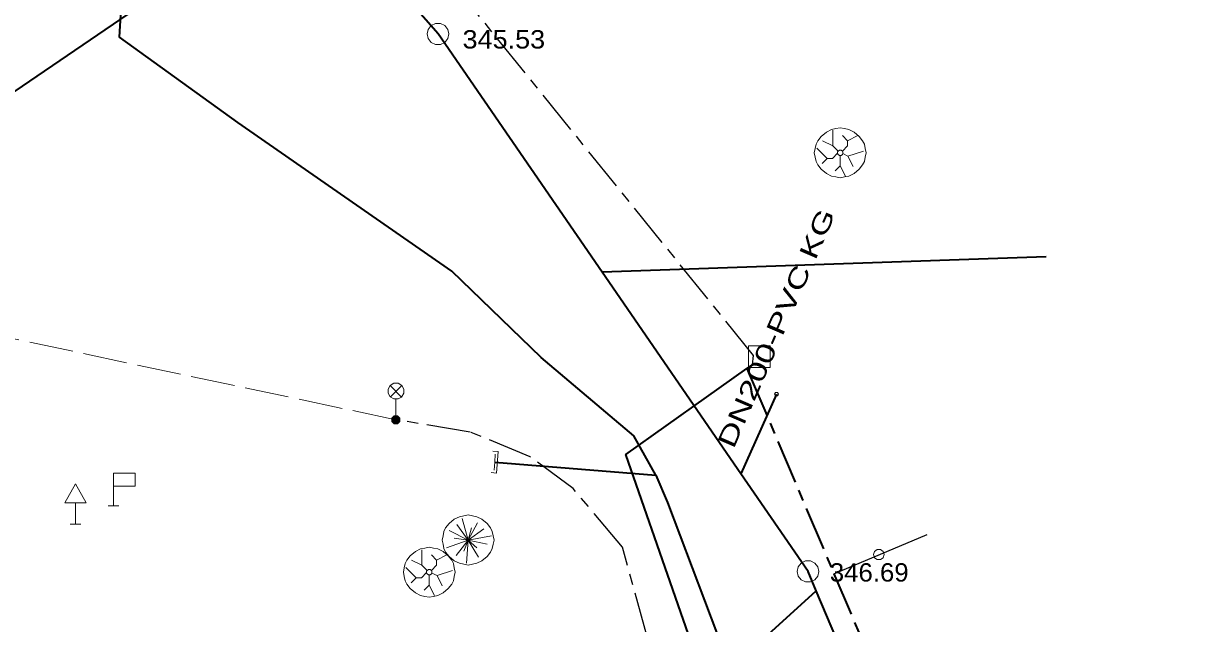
# Model space of a CAD drawing. Extents: x -763495 to -763378, y -1031793 to -1031652.
# Drawn here: x -763444.2 to -763390, y -1031751.8 to -1031723.9 of the extents above; entities that cross this region are included whole.
import ezdxf
from ezdxf.enums import TextEntityAlignment as Align

# ---------------------------------------------------------------- set-up
doc = ezdxf.new("R2010")
doc.units = 0
doc.header["$LTSCALE"] = 0.34
doc.linetypes.add('LONG_DASH_SHORT_DASH', pattern=[9.9, 6, -1.2, 1.5, -1.2])
doc.linetypes.add('LONG_DASHED', pattern=[7.5, 6, -1.5])
for name, color, linetype, lineweight in [('23', 7, 'Continuous', 13), ('27', 7, 'Continuous', 13), ('33', 7, 'Continuous', 13), ('34', 7, 'Continuous', 13), ('40', 7, 'Continuous', 13), ('43', 7, 'Continuous', 25), ('44', 7, 'Continuous', 35), ('45', 7, 'Continuous', 13), ('51', 7, 'LONG_DASH_SHORT_DASH', 25), ('59', 7, 'LONG_DASHED', 13)]:
    doc.layers.add(name, color=color, linetype=linetype, lineweight=lineweight)

msp = doc.modelspace()

# ---------------------------------------------------------------- linework, layer by layer
at = {"layer": '23'}
for p, q in [((-763440.31, -1031746.29), (-763439.81, -1031746.29)), ((-763442.07, -1031747.15), (-763441.57, -1031747.15))]:
    msp.add_line(p, q, dxfattribs=at)
for points in [[(-763440.06, -1031746.29), (-763440.06, -1031744.79), (-763439.06, -1031744.79), (-763439.06, -1031745.39), (-763440.06, -1031745.39)], [(-763441.82, -1031747.15), (-763441.82, -1031746.15), (-763441.32, -1031746.15), (-763441.82, -1031745.275), (-763442.32, -1031746.15), (-763441.82, -1031746.15)]]:
    msp.add_lwpolyline(points, dxfattribs=at)
at = {"layer": '27'}
for p, q in [((-763406.07, -1031729.38), (-763406.31, -1031729.14)), ((-763406.05, -1031730.1), (-763405.33, -1031729.86)), ((-763407.01, -1031730.2), (-763407.25, -1031730.44)), ((-763406.41, -1031730.54), (-763406.17, -1031731.02)), ((-763425.1, -1031748.81), (-763425.34, -1031748.57)), ((-763426.04, -1031749.63), (-763426.28, -1031749.87)), ((-763425.08, -1031749.53), (-763424.36, -1031749.29)), ((-763425.44, -1031749.97), (-763425.2, -1031750.45))]:
    msp.add_line(p, q, dxfattribs=at)
for points in [[(-763407.61, -1031729.94), (-763407.57, -1031729.74), (-763407.53, -1031729.54), (-763407.45, -1031729.38), (-763407.29, -1031729.18), (-763407.05, -1031728.98), (-763406.81, -1031728.86), (-763406.61, -1031728.82), (-763406.41, -1031728.78), (-763406.21, -1031728.82), (-763406.01, -1031728.86), (-763405.77, -1031728.98), (-763405.53, -1031729.18), (-763405.37, -1031729.38), (-763405.29, -1031729.54), (-763405.25, -1031729.74), (-763405.21, -1031729.94), (-763405.25, -1031730.14), (-763405.29, -1031730.34), (-763405.37, -1031730.5), (-763405.53, -1031730.7), (-763405.77, -1031730.9), (-763406.01, -1031731.02), (-763406.21, -1031731.06), (-763406.41, -1031731.1), (-763406.61, -1031731.06), (-763406.81, -1031731.02), (-763407.05, -1031730.9), (-763407.29, -1031730.7), (-763407.45, -1031730.5), (-763407.53, -1031730.34), (-763407.57, -1031730.14)], [(-763406.53, -1031729.94), (-763406.53, -1031729.9), (-763406.51, -1031729.86), (-763406.45, -1031729.82), (-763406.37, -1031729.82), (-763406.31, -1031729.86), (-763406.29, -1031729.9), (-763406.29, -1031729.98), (-763406.31, -1031730.02), (-763406.37, -1031730.06), (-763406.45, -1031730.06), (-763406.51, -1031730.02), (-763406.53, -1031729.98)], [(-763424.84, -1031747.88), (-763424.8, -1031747.68), (-763424.76, -1031747.48), (-763424.68, -1031747.32), (-763424.52, -1031747.12), (-763424.28, -1031746.92), (-763424.04, -1031746.8), (-763423.84, -1031746.76), (-763423.64, -1031746.72), (-763423.44, -1031746.76), (-763423.24, -1031746.8), (-763423, -1031746.92), (-763422.76, -1031747.12), (-763422.6, -1031747.32), (-763422.52, -1031747.48), (-763422.48, -1031747.68), (-763422.44, -1031747.88), (-763422.48, -1031748.08), (-763422.52, -1031748.28), (-763422.6, -1031748.44), (-763422.76, -1031748.64), (-763423, -1031748.84), (-763423.24, -1031748.96), (-763423.44, -1031749), (-763423.64, -1031749.04), (-763423.84, -1031749), (-763424.04, -1031748.96), (-763424.28, -1031748.84), (-763424.52, -1031748.64), (-763424.68, -1031748.44), (-763424.76, -1031748.28), (-763424.8, -1031748.08)], [(-763426.64, -1031749.37), (-763426.6, -1031749.17), (-763426.56, -1031748.97), (-763426.48, -1031748.81), (-763426.32, -1031748.61), (-763426.08, -1031748.41), (-763425.84, -1031748.29), (-763425.64, -1031748.25), (-763425.44, -1031748.21), (-763425.24, -1031748.25), (-763425.04, -1031748.29), (-763424.8, -1031748.41), (-763424.56, -1031748.61), (-763424.4, -1031748.81), (-763424.32, -1031748.97), (-763424.28, -1031749.17), (-763424.24, -1031749.37), (-763424.28, -1031749.57), (-763424.32, -1031749.77), (-763424.4, -1031749.93), (-763424.56, -1031750.13), (-763424.8, -1031750.33), (-763425.04, -1031750.45), (-763425.24, -1031750.49), (-763425.44, -1031750.53), (-763425.64, -1031750.49), (-763425.84, -1031750.45), (-763426.08, -1031750.33), (-763426.32, -1031750.13), (-763426.48, -1031749.93), (-763426.56, -1031749.77), (-763426.6, -1031749.57)], [(-763425.56, -1031749.37), (-763425.56, -1031749.33), (-763425.54, -1031749.29), (-763425.48, -1031749.25), (-763425.4, -1031749.25), (-763425.34, -1031749.29), (-763425.32, -1031749.33), (-763425.32, -1031749.41), (-763425.34, -1031749.45), (-763425.4, -1031749.49), (-763425.48, -1031749.49), (-763425.54, -1031749.45), (-763425.56, -1031749.41)]]:
    msp.add_lwpolyline(points, close=True, dxfattribs=at)
for points in [[(-763406.51, -1031729.86), (-763406.75, -1031729.62), (-763406.75, -1031728.9), (-763406.75, -1031729.62), (-763407.23, -1031729.38)], [(-763406.31, -1031729.86), (-763406.07, -1031729.62), (-763406.07, -1031729.38), (-763405.59, -1031729.14)], [(-763406.53, -1031729.96), (-763406.77, -1031730.2), (-763407.01, -1031730.2), (-763407.49, -1031729.72)], [(-763406.41, -1031730.06), (-763406.41, -1031730.54), (-763406.65, -1031730.78)], [(-763406.29, -1031729.98), (-763406.05, -1031730.1), (-763405.81, -1031730.58)], [(-763423.48, -1031747.32), (-763423.64, -1031747.88), (-763423.92, -1031746.88), (-763423.64, -1031747.88), (-763424.16, -1031747.16), (-763423.64, -1031747.88), (-763424.52, -1031747.44), (-763423.64, -1031747.88), (-763424.28, -1031747.8), (-763423.64, -1031747.88), (-763424.64, -1031748.24), (-763423.64, -1031747.88), (-763424.2, -1031748.6), (-763423.64, -1031747.88), (-763423.84, -1031748.4), (-763423.64, -1031747.88), (-763423.72, -1031748.96), (-763423.64, -1031747.88), (-763423.16, -1031748.68), (-763423.64, -1031747.88), (-763423.24, -1031748.24), (-763423.64, -1031747.88), (-763422.76, -1031748.08), (-763423.64, -1031747.88), (-763422.56, -1031747.68), (-763423.64, -1031747.88), (-763422.92, -1031747.36), (-763423.64, -1031747.88), (-763423.2, -1031747.08), (-763423.64, -1031747.88)], [(-763425.54, -1031749.29), (-763425.78, -1031749.05), (-763425.78, -1031748.33), (-763425.78, -1031749.05), (-763426.26, -1031748.81)], [(-763425.34, -1031749.29), (-763425.1, -1031749.05), (-763425.1, -1031748.81), (-763424.62, -1031748.57)], [(-763425.56, -1031749.39), (-763425.8, -1031749.63), (-763426.04, -1031749.63), (-763426.52, -1031749.15)], [(-763425.44, -1031749.49), (-763425.44, -1031749.97), (-763425.68, -1031750.21)], [(-763425.32, -1031749.41), (-763425.08, -1031749.53), (-763424.84, -1031750.01)]]:
    msp.add_lwpolyline(points, dxfattribs=at)
at = {"layer": '33'}
for points in [[(-763410.66, -1031738.88), (-763409.66, -1031738.88), (-763409.66, -1031739.88), (-763410.66, -1031739.88)], [(-763404.545, -1031748.32), (-763404.42, -1031748.41), (-763404.37, -1031748.555), (-763404.42, -1031748.7), (-763404.545, -1031748.79), (-763404.7, -1031748.79), (-763404.825, -1031748.7), (-763404.875, -1031748.555), (-763404.825, -1031748.41), (-763404.7, -1031748.32)]]:
    msp.add_lwpolyline(points, close=True, dxfattribs=at)
at = {"layer": '34'}
for points in [[(-763424.921, -1031723.952), (-763424.721, -1031724.047), (-763424.581, -1031724.222), (-763424.531, -1031724.437), (-763424.581, -1031724.652), (-763424.721, -1031724.827), (-763424.921, -1031724.922), (-763425.146, -1031724.922), (-763425.346, -1031724.827), (-763425.486, -1031724.652), (-763425.536, -1031724.437), (-763425.486, -1031724.222), (-763425.346, -1031724.047), (-763425.146, -1031723.952)], [(-763409.445, -1031741.13), (-763409.409, -1031741.051), (-763409.321, -1031741.045), (-763409.27, -1031741.119), (-763409.307, -1031741.199), (-763409.394, -1031741.204)], [(-763407.787, -1031748.852), (-763407.587, -1031748.947), (-763407.447, -1031749.122), (-763407.397, -1031749.337), (-763407.447, -1031749.552), (-763407.587, -1031749.727), (-763407.787, -1031749.822), (-763408.012, -1031749.822), (-763408.212, -1031749.727), (-763408.352, -1031749.552), (-763408.402, -1031749.337), (-763408.352, -1031749.122), (-763408.212, -1031748.947), (-763408.012, -1031748.852)]]:
    msp.add_lwpolyline(points, close=True, dxfattribs=at)
at = {"layer": '40'}
for p, q in [((-763426.73, -1031741.26), (-763427.245, -1031740.72)), ((-763427.24, -1031741.25), (-763426.715, -1031740.72))]:
    msp.add_line(p, q, dxfattribs=at)
for points in [[(-763426.985, -1031742.125), (-763426.985, -1031741.49), (-763426.985, -1031741.345), (-763427.08, -1031741.345), (-763427.245, -1031741.25), (-763427.345, -1031741.08), (-763427.345, -1031740.885), (-763427.25, -1031740.715), (-763427.08, -1031740.62), (-763426.885, -1031740.62), (-763426.715, -1031740.715), (-763426.62, -1031740.885), (-763426.62, -1031741.08), (-763426.73, -1031741.26), (-763426.885, -1031741.345), (-763426.98, -1031741.345)], [(-763426.98, -1031742.125), (-763426.905, -1031742.125), (-763426.795, -1031742.235), (-763426.795, -1031742.39), (-763426.905, -1031742.5), (-763427.06, -1031742.5), (-763427.17, -1031742.39), (-763427.17, -1031742.235), (-763427.06, -1031742.125), (-763426.985, -1031742.125), (-763426.91, -1031742.145), (-763427.06, -1031742.145), (-763427.09, -1031742.17), (-763426.89, -1031742.17), (-763426.85, -1031742.21), (-763427.13, -1031742.21), (-763427.15, -1031742.25), (-763426.825, -1031742.25), (-763426.825, -1031742.29), (-763427.15, -1031742.29), (-763427.15, -1031742.33), (-763426.825, -1031742.33), (-763426.825, -1031742.37), (-763427.145, -1031742.37), (-763427.125, -1031742.41), (-763426.845, -1031742.41), (-763426.885, -1031742.45), (-763427.085, -1031742.45), (-763427.06, -1031742.47), (-763426.905, -1031742.47)]]:
    msp.add_lwpolyline(points, dxfattribs=at)
at = {"layer": '43'}
msp.add_line((-763406.7, -1031749.44), (-763402.39, -1031747.62), dxfattribs=at)
at = {"layer": '43', "linetype": 'LONG_DASH_SHORT_DASH'}
msp.add_lwpolyline([(-763410.479, -1031739.762), (-763410.419, -1031739.329), (-763429.088, -1031716.231), (-763434.935, -1031708.998), (-763432.635, -1031699.413), (-763467.811, -1031684.74), (-763473.63, -1031678.84), (-763474.846, -1031677.495), (-763485.18, -1031666.004), (-763494.195, -1031657.611)], dxfattribs=at)
at = {"layer": '43', "lineweight": 35}
for points in [[(-763428.03, -1031715.48), (-763438.34, -1031722.78), (-763475.986, -1031748.441)], [(-763400.132, -1031790.86), (-763400.38, -1031790.12), (-763403.73, -1031780.13), (-763407.14, -1031770.35), (-763416.343, -1031743.922), (-763410.726, -1031739.937), (-763410.479, -1031739.762)]]:
    msp.add_lwpolyline(points, dxfattribs=at)
at = {"layer": '43', "linetype": 'LONG_DASH_SHORT_DASH', "lineweight": 35}
msp.add_lwpolyline([(-763410.726, -1031739.937), (-763410.61, -1031740.22), (-763406.7, -1031749.44), (-763399.52, -1031766.42), (-763391.59, -1031785.17), (-763390, -1031788.925)], dxfattribs=at)
at = {"layer": '44'}
for p, q in [((-763396.876, -1031734.76), (-763417.435, -1031735.477)), ((-763409.358, -1031741.125), (-763411.012, -1031744.81)), ((-763413.291, -1031755.481), (-763407.519, -1031750.23))]:
    msp.add_line(p, q, dxfattribs=at)
msp.add_lwpolyline([(-763391.618, -1031789.234), (-763393.492, -1031784.483), (-763400.133, -1031767.646), (-763400.737, -1031766.222), (-763405.172, -1031755.763), (-763407.519, -1031750.23), (-763407.897, -1031749.337), (-763411.012, -1031744.81), (-763417.435, -1031735.477), (-763425.031, -1031724.437), (-763457.995, -1031686.981)], dxfattribs=at)
at = {"layer": '45'}
for q in [(-763422.44, -1031744.644), (-763422.38, -1031743.896)]:
    msp.add_line((-763422.41, -1031744.27), q, dxfattribs=at)
at = {"layer": '45', "lineweight": 35}
msp.add_line((-763422.41, -1031744.27), (-763414.95, -1031744.87), dxfattribs=at)
for points in [[(-763414.95, -1031744.87), (-763415.97, -1031743.05), (-763420.26, -1031739.42), (-763424.39, -1031735.42), (-763434.3, -1031728.54), (-763439.78, -1031724.58), (-763439.677, -1031722.759)], [(-763414.95, -1031744.87), (-763414.41, -1031746.14), (-763409.84, -1031758.25), (-763405.4, -1031770.86)]]:
    msp.add_lwpolyline(points, dxfattribs=at)
at = {"layer": '45'}
msp.add_lwpolyline([(-763422.495, -1031743.762), (-763422.245, -1031743.782), (-763422.325, -1031744.778), (-763422.575, -1031744.758)], dxfattribs=at)
at = {"layer": '51'}
msp.add_lwpolyline([(-763413.57, -1031758.8), (-763416.497, -1031748.207), (-763418.78, -1031745.488), (-763420.771, -1031744.021), (-763423.544, -1031742.877), (-763426.98, -1031742.31)], dxfattribs=at)
at = {"layer": '59'}
msp.add_lwpolyline([(-763426.98, -1031742.31), (-763448.83, -1031737.68), (-763466.1, -1031734.52), (-763481.063, -1031738.7)], dxfattribs=at)

# ---------------------------------------------------------------- texts
at = {"layer": '44'}
for s, width, p in [('345.53', 1.1, (-763421.986, -1031725.109)), ('346.69', 1.05, (-763405.066, -1031749.805))]:
    msp.add_text(s, height=0.85, dxfattribs=dict(at, width=width)).set_placement(p, align=Align.CENTER)
at = {"layer": '44', "width": 1.45}
msp.add_text('DN200-PVC KG', height=0.85, rotation=66.578, dxfattribs=at).set_placement((-763408.98, -1031738.23), align=Align.CENTER)

doc.saveas('drawing.dxf')
